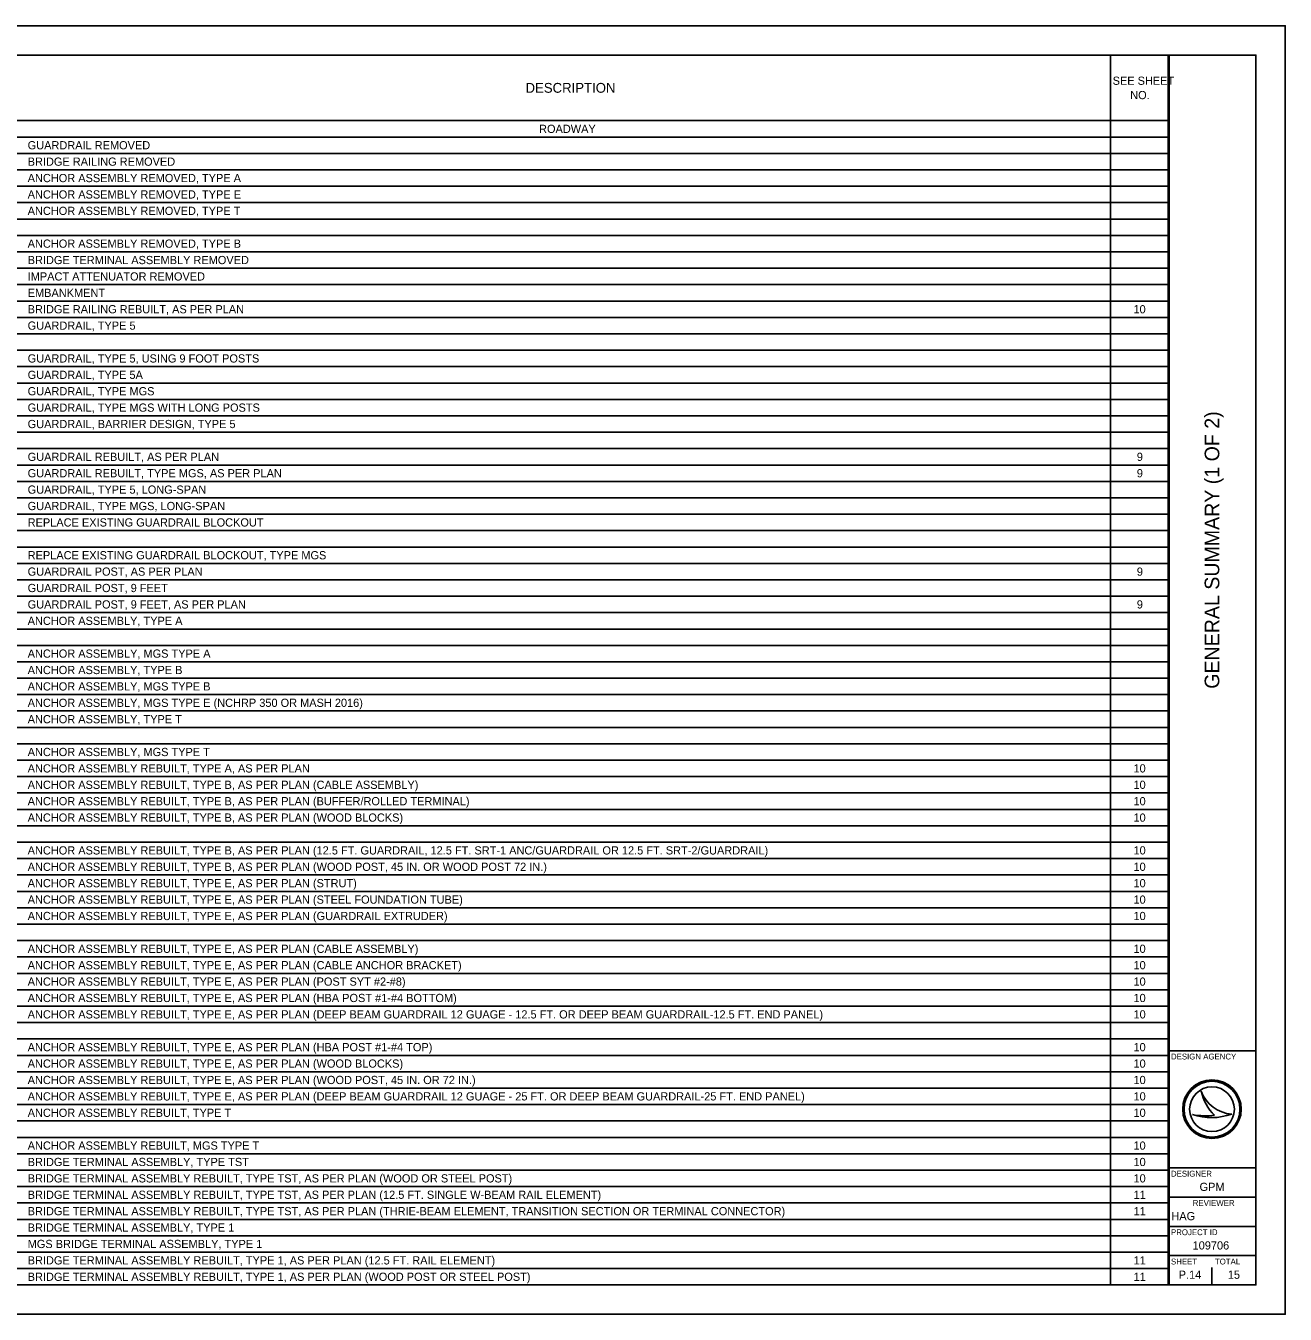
# Model space of a CAD drawing. Extents: x 0 to 34, y 0 to 22.
# Drawn here: x 12.5 to 34, y 0 to 22 of the extents above; entities that cross this region are included whole.
import ezdxf

# ---------------------------------------------------------------- set-up
doc = ezdxf.new("R2010")
doc.units = 0
for name, color, linetype in [('Default', 7, 'Continuous'), ('SH_Border', 7, 'Continuous'), ('SH_Cut_Line', 7, 'Continuous'), ('SH_Data', 7, 'Continuous')]:
    doc.layers.add(name, color=color, linetype=linetype)

msp = doc.modelspace()

# ---------------------------------------------------------------- linework, layer by layer
at = {"layer": 'Default'}
for p, q in [((1.5, 21.5), (32.02, 21.5)), ((31.015, 21.5), (31.015, 0.5)), ((32.02, 21.5), (32.02, 0.5)), ((1.5, 20.38), (32.02, 20.38)), ((1.5, 20.1), (32.02, 20.1)), ((1.5, 19.82), (32.02, 19.82)), ((1.5, 19.54), (32.02, 19.54)), ((1.5, 19.26), (32.02, 19.26)), ((1.5, 18.98), (32.02, 18.98)), ((1.5, 18.7), (32.02, 18.7)), ((1.5, 18.42), (32.02, 18.42)), ((1.5, 18.14), (32.02, 18.14)), ((1.5, 17.86), (32.02, 17.86)), ((1.5, 17.58), (32.02, 17.58)), ((1.5, 17.3), (32.02, 17.3)), ((1.5, 17.02), (32.02, 17.02)), ((1.5, 16.74), (32.02, 16.74)), ((1.5, 16.46), (32.02, 16.46)), ((1.5, 16.18), (32.02, 16.18)), ((1.5, 15.9), (32.02, 15.9)), ((1.5, 15.62), (32.02, 15.62)), ((1.5, 15.34), (32.02, 15.34)), ((1.5, 15.06), (32.02, 15.06)), ((1.5, 14.78), (32.02, 14.78)), ((1.5, 14.5), (32.02, 14.5)), ((1.5, 14.22), (32.02, 14.22)), ((1.5, 13.94), (32.02, 13.94)), ((1.5, 13.66), (32.02, 13.66)), ((1.5, 13.38), (32.02, 13.38)), ((1.5, 13.1), (32.02, 13.1)), ((1.5, 12.82), (32.02, 12.82)), ((1.5, 12.54), (32.02, 12.54)), ((1.5, 12.26), (32.02, 12.26)), ((1.5, 11.98), (32.02, 11.98)), ((1.5, 11.7), (32.02, 11.7)), ((1.5, 11.42), (32.02, 11.42)), ((1.5, 11.14), (32.02, 11.14)), ((1.5, 10.86), (32.02, 10.86)), ((1.5, 10.58), (32.02, 10.58)), ((1.5, 10.3), (32.02, 10.3)), ((1.5, 10.02), (32.02, 10.02)), ((1.5, 9.74), (32.02, 9.74)), ((1.5, 9.46), (32.02, 9.46)), ((1.5, 9.18), (32.02, 9.18)), ((1.5, 8.9), (32.02, 8.9)), ((1.5, 8.62), (32.02, 8.62)), ((1.5, 8.34), (32.02, 8.34)), ((1.5, 8.06), (32.02, 8.06)), ((1.5, 7.78), (32.02, 7.78)), ((1.5, 7.5), (32.02, 7.5)), ((1.5, 7.22), (32.02, 7.22)), ((1.5, 6.94), (32.02, 6.94)), ((1.5, 6.66), (32.02, 6.66)), ((1.5, 6.38), (32.02, 6.38)), ((1.5, 6.1), (32.02, 6.1)), ((1.5, 5.82), (32.02, 5.82)), ((1.5, 5.54), (32.02, 5.54)), ((1.5, 5.26), (32.02, 5.26)), ((1.5, 4.98), (32.02, 4.98)), ((1.5, 4.7), (32.02, 4.7)), ((1.5, 4.42), (32.02, 4.42)), ((1.5, 4.14), (32.02, 4.14)), ((1.5, 3.86), (32.02, 3.86)), ((1.5, 3.58), (32.02, 3.58)), ((1.5, 3.3), (32.02, 3.3)), ((1.5, 3.02), (32.02, 3.02)), ((1.5, 2.74), (32.02, 2.74)), ((1.5, 2.46), (32.02, 2.46)), ((1.5, 2.18), (32.02, 2.18)), ((1.5, 1.9), (32.02, 1.9)), ((1.5, 1.62), (32.02, 1.62)), ((1.5, 1.34), (32.02, 1.34)), ((1.5, 1.06), (32.02, 1.06)), ((1.5, 0.78), (32.02, 0.78)), ((1.5, 0.5), (32.02, 0.5))]:
    msp.add_line(p, q, dxfattribs=at)
at = {"layer": 'SH_Border'}
for p, q in [((32, 0.5), (32, 21.5)), ((32, 4.5), (33.5, 4.5)), ((32, 2.5), (33.5, 2.5)), ((32, 2), (33.5, 2)), ((32, 1.5), (33.5, 1.5)), ((32, 1), (33.5, 1))]:
    msp.add_line(p, q, dxfattribs=at)
msp.add_lwpolyline([(1.5, 21.5), (33.5, 21.5), (33.5, 0.5), (1.5, 0.5)], close=True, dxfattribs=at)
at = {"layer": 'SH_Cut_Line'}
msp.add_lwpolyline([(0, 0), (34, 0), (34, 22), (0, 22)], close=True, dxfattribs=at)
at = {"layer": 'SH_Data'}
for p, q in [((32.567, 3.81), (32.567, 3.81)), ((32.417, 3.41), (32.417, 3.41)), ((32.75, 3.5), (32.75, 3.5)), ((33.087, 3.419), (33.087, 3.419)), ((32.375, 0.675), (32.375, 0.675)), ((32.75, 0.5), (32.75, 0.8))]:
    msp.add_line(p, q, dxfattribs=at)
for radius in [0.5, 0.477, 0.477, 0.382]:
    msp.add_circle((32.75, 3.5), radius, dxfattribs=at)
for centre, radius, start, end in [((33.116, 3.998), 0.58, 198.9257, 198.9319), ((33.347, 3.97), 0.796, 191.6379, 191.6421), ((33.116, 3.998), 0.58, 198.9319, 267.1657), ((33.347, 3.97), 0.796, 191.6421, 226.0947), ((32.739, 4.37), 1.013, 251.4576, 290.0832), ((32.648, 4.654), 1.266, 259.4964, 259.4995), ((32.739, 4.37), 1.013, 251.4527, 251.4576), ((32.648, 4.654), 1.266, 259.4995, 276.6672)]:
    msp.add_arc(centre, radius, start, end, dxfattribs=at)

# ---------------------------------------------------------------- texts
at = {"layer": 'Default'}
for s, height, p in [('SEE SHEET ', 0.14, (31.054, 20.992)), ('DESCRIPTION', 0.168, (21.033, 20.856)), ('NO.', 0.14, (31.354, 20.747)), ('ROADWAY', 0.14, (21.264, 20.17)), ('GUARDRAIL REMOVED', 0.14, (12.535, 19.89)), ('BRIDGE RAILING REMOVED', 0.14, (12.535, 19.61)), ('ANCHOR ASSEMBLY REMOVED, TYPE A', 0.14, (12.535, 19.33)), ('ANCHOR ASSEMBLY REMOVED, TYPE E', 0.14, (12.535, 19.05)), ('ANCHOR ASSEMBLY REMOVED, TYPE T', 0.14, (12.535, 18.77)), ('ANCHOR ASSEMBLY REMOVED, TYPE B', 0.14, (12.535, 18.21)), ('BRIDGE TERMINAL ASSEMBLY REMOVED', 0.14, (12.535, 17.93)), ('IMPACT ATTENUATOR REMOVED', 0.14, (12.535, 17.65)), ('EMBANKMENT', 0.14, (12.535, 17.37)), ('BRIDGE RAILING REBUILT, AS PER PLAN', 0.14, (12.535, 17.09)), ('10', 0.14, (31.41, 17.09)), ('GUARDRAIL, TYPE 5', 0.14, (12.535, 16.81)), ('GUARDRAIL, TYPE 5, USING 9 FOOT POSTS', 0.14, (12.535, 16.25)), ('GUARDRAIL, TYPE 5A', 0.14, (12.535, 15.97)), ('GUARDRAIL, TYPE MGS', 0.14, (12.535, 15.69)), ('GUARDRAIL, TYPE MGS WITH LONG POSTS', 0.14, (12.535, 15.41)), ('GUARDRAIL, BARRIER DESIGN, TYPE 5', 0.14, (12.535, 15.13)), ('GUARDRAIL REBUILT, AS PER PLAN', 0.14, (12.535, 14.57)), ('9', 0.14, (31.467, 14.57)), ('GUARDRAIL REBUILT, TYPE MGS, AS PER PLAN', 0.14, (12.535, 14.29)), ('9', 0.14, (31.467, 14.29)), ('GUARDRAIL, TYPE 5, LONG-SPAN', 0.14, (12.535, 14.01)), ('GUARDRAIL, TYPE MGS, LONG-SPAN', 0.14, (12.535, 13.73)), ('REPLACE EXISTING GUARDRAIL BLOCKOUT', 0.14, (12.535, 13.45)), ('REPLACE EXISTING GUARDRAIL BLOCKOUT, TYPE MGS', 0.14, (12.535, 12.89)), ('GUARDRAIL POST, AS PER PLAN', 0.14, (12.535, 12.61)), ('9', 0.14, (31.467, 12.61)), ('GUARDRAIL POST, 9 FEET', 0.14, (12.535, 12.33)), ('GUARDRAIL POST, 9 FEET, AS PER PLAN', 0.14, (12.535, 12.05)), ('9', 0.14, (31.467, 12.05)), ('ANCHOR ASSEMBLY, TYPE A', 0.14, (12.535, 11.77)), ('ANCHOR ASSEMBLY, MGS TYPE A', 0.14, (12.535, 11.21)), ('ANCHOR ASSEMBLY, TYPE B', 0.14, (12.535, 10.93)), ('ANCHOR ASSEMBLY, MGS TYPE B', 0.14, (12.535, 10.65)), ('ANCHOR ASSEMBLY, MGS TYPE E (NCHRP 350 OR MASH 2016)', 0.14, (12.535, 10.37)), ('ANCHOR ASSEMBLY, TYPE T', 0.14, (12.535, 10.09)), ('ANCHOR ASSEMBLY, MGS TYPE T', 0.14, (12.535, 9.53)), ('ANCHOR ASSEMBLY REBUILT, TYPE A, AS PER PLAN', 0.14, (12.535, 9.25)), ('10', 0.14, (31.41, 9.25)), ('ANCHOR ASSEMBLY REBUILT, TYPE B, AS PER PLAN (CABLE ASSEMBLY)', 0.14, (12.535, 8.97)), ('10', 0.14, (31.41, 8.97)), ('ANCHOR ASSEMBLY REBUILT, TYPE B, AS PER PLAN (BUFFER/ROLLED TERMINAL)', 0.14, (12.535, 8.69)), ('10', 0.14, (31.41, 8.69)), ('ANCHOR ASSEMBLY REBUILT, TYPE B, AS PER PLAN (WOOD BLOCKS)', 0.14, (12.535, 8.41)), ('10', 0.14, (31.41, 8.41)), ('ANCHOR ASSEMBLY REBUILT, TYPE B, AS PER PLAN (12.5 FT. GUARDRAIL, 12.5 FT. SRT-1 ANC/GUARDRAIL OR 12.5 FT. SRT-2/GUARDRAIL)', 0.14, (12.535, 7.85)), ('10', 0.14, (31.41, 7.85)), ('ANCHOR ASSEMBLY REBUILT, TYPE B, AS PER PLAN (WOOD POST, 45 IN. OR WOOD POST 72 IN.)', 0.14, (12.535, 7.57)), ('10', 0.14, (31.41, 7.57)), ('ANCHOR ASSEMBLY REBUILT, TYPE E, AS PER PLAN (STRUT)', 0.14, (12.535, 7.29)), ('10', 0.14, (31.41, 7.29)), ('ANCHOR ASSEMBLY REBUILT, TYPE E, AS PER PLAN (STEEL FOUNDATION TUBE)', 0.14, (12.535, 7.01)), ('10', 0.14, (31.41, 7.01)), ('ANCHOR ASSEMBLY REBUILT, TYPE E, AS PER PLAN (GUARDRAIL EXTRUDER)', 0.14, (12.535, 6.73)), ('10', 0.14, (31.41, 6.73)), ('ANCHOR ASSEMBLY REBUILT, TYPE E, AS PER PLAN (CABLE ASSEMBLY)', 0.14, (12.535, 6.17)), ('10', 0.14, (31.41, 6.17)), ('ANCHOR ASSEMBLY REBUILT, TYPE E, AS PER PLAN (CABLE ANCHOR BRACKET)', 0.14, (12.535, 5.89)), ('10', 0.14, (31.41, 5.89)), ('ANCHOR ASSEMBLY REBUILT, TYPE E, AS PER PLAN (POST SYT #2-#8)', 0.14, (12.535, 5.61)), ('10', 0.14, (31.41, 5.61)), ('ANCHOR ASSEMBLY REBUILT, TYPE E, AS PER PLAN (HBA POST #1-#4 BOTTOM)', 0.14, (12.535, 5.33)), ('10', 0.14, (31.41, 5.33)), ('ANCHOR ASSEMBLY REBUILT, TYPE E, AS PER PLAN (DEEP BEAM GUARDRAIL 12 GUAGE - 12.5 FT. OR DEEP BEAM GUARDRAIL-12.5 FT. END PANEL)', 0.14, (12.535, 5.05)), ('10', 0.14, (31.41, 5.05)), ('ANCHOR ASSEMBLY REBUILT, TYPE E, AS PER PLAN (HBA POST #1-#4 TOP)', 0.14, (12.535, 4.49)), ('10', 0.14, (31.41, 4.49)), ('ANCHOR ASSEMBLY REBUILT, TYPE E, AS PER PLAN (WOOD BLOCKS)', 0.14, (12.535, 4.21)), ('10', 0.14, (31.41, 4.21)), ('ANCHOR ASSEMBLY REBUILT, TYPE E, AS PER PLAN (WOOD POST, 45 IN. OR 72 IN.)', 0.14, (12.535, 3.93)), ('10', 0.14, (31.41, 3.93)), ('ANCHOR ASSEMBLY REBUILT, TYPE E, AS PER PLAN (DEEP BEAM GUARDRAIL 12 GUAGE - 25 FT. OR DEEP BEAM GUARDRAIL-25 FT. END PANEL)', 0.14, (12.535, 3.65)), ('10', 0.14, (31.41, 3.65)), ('ANCHOR ASSEMBLY REBUILT, TYPE T', 0.14, (12.535, 3.37)), ('10', 0.14, (31.41, 3.37)), ('ANCHOR ASSEMBLY REBUILT, MGS TYPE T', 0.14, (12.535, 2.81)), ('10', 0.14, (31.41, 2.81)), ('BRIDGE TERMINAL ASSEMBLY, TYPE TST', 0.14, (12.535, 2.53)), ('10', 0.14, (31.41, 2.53)), ('BRIDGE TERMINAL ASSEMBLY REBUILT, TYPE TST, AS PER PLAN (WOOD OR STEEL POST)', 0.14, (12.535, 2.25)), ('10', 0.14, (31.41, 2.25)), ('BRIDGE TERMINAL ASSEMBLY REBUILT, TYPE TST, AS PER PLAN (12.5 FT. SINGLE W-BEAM RAIL ELEMENT)', 0.14, (12.535, 1.97)), ('11', 0.14, (31.412, 1.97)), ('BRIDGE TERMINAL ASSEMBLY REBUILT, TYPE TST, AS PER PLAN (THRIE-BEAM ELEMENT, TRANSITION SECTION OR TERMINAL CONNECTOR)', 0.14, (12.535, 1.69)), ('11', 0.14, (31.412, 1.69)), ('BRIDGE TERMINAL ASSEMBLY, TYPE 1', 0.14, (12.535, 1.41)), ('MGS BRIDGE TERMINAL ASSEMBLY, TYPE 1', 0.14, (12.535, 1.13)), ('BRIDGE TERMINAL ASSEMBLY REBUILT, TYPE 1, AS PER PLAN (12.5 FT. RAIL ELEMENT)', 0.14, (12.535, 0.85)), ('11', 0.14, (31.412, 0.85)), ('BRIDGE TERMINAL ASSEMBLY REBUILT, TYPE 1, AS PER PLAN (WOOD POST OR STEEL POST)', 0.14, (12.535, 0.57)), ('11', 0.14, (31.412, 0.57))]:
    msp.add_text(s, height=height, dxfattribs=at).set_placement(p)
at = {"layer": 'SH_Data'}
msp.add_text('GENERAL SUMMARY (1 OF 2)', height=0.25, rotation=90, dxfattribs=at).set_placement((32.875, 10.68))
for s, height, p in [('DESIGN AGENCY', 0.1, (32.05, 4.35)), ('DESIGNER', 0.1, (32.05, 2.35)), ('GPM', 0.14, (32.538, 2.105)), ('REVIEWER', 0.1, (32.422, 1.85)), ('HAG', 0.14, (32.057, 1.605)), ('PROJECT ID', 0.1, (32.05, 1.35)), ('109706', 0.14, (32.419, 1.105)), ('SHEET', 0.1, (32.05, 0.85)), ('TOTAL', 0.1, (32.8, 0.85)), ('P.14', 0.14, (32.182, 0.605)), ('15', 0.14, (33.02, 0.605))]:
    msp.add_text(s, height=height, dxfattribs=at).set_placement(p)

doc.saveas('drawing.dxf')
